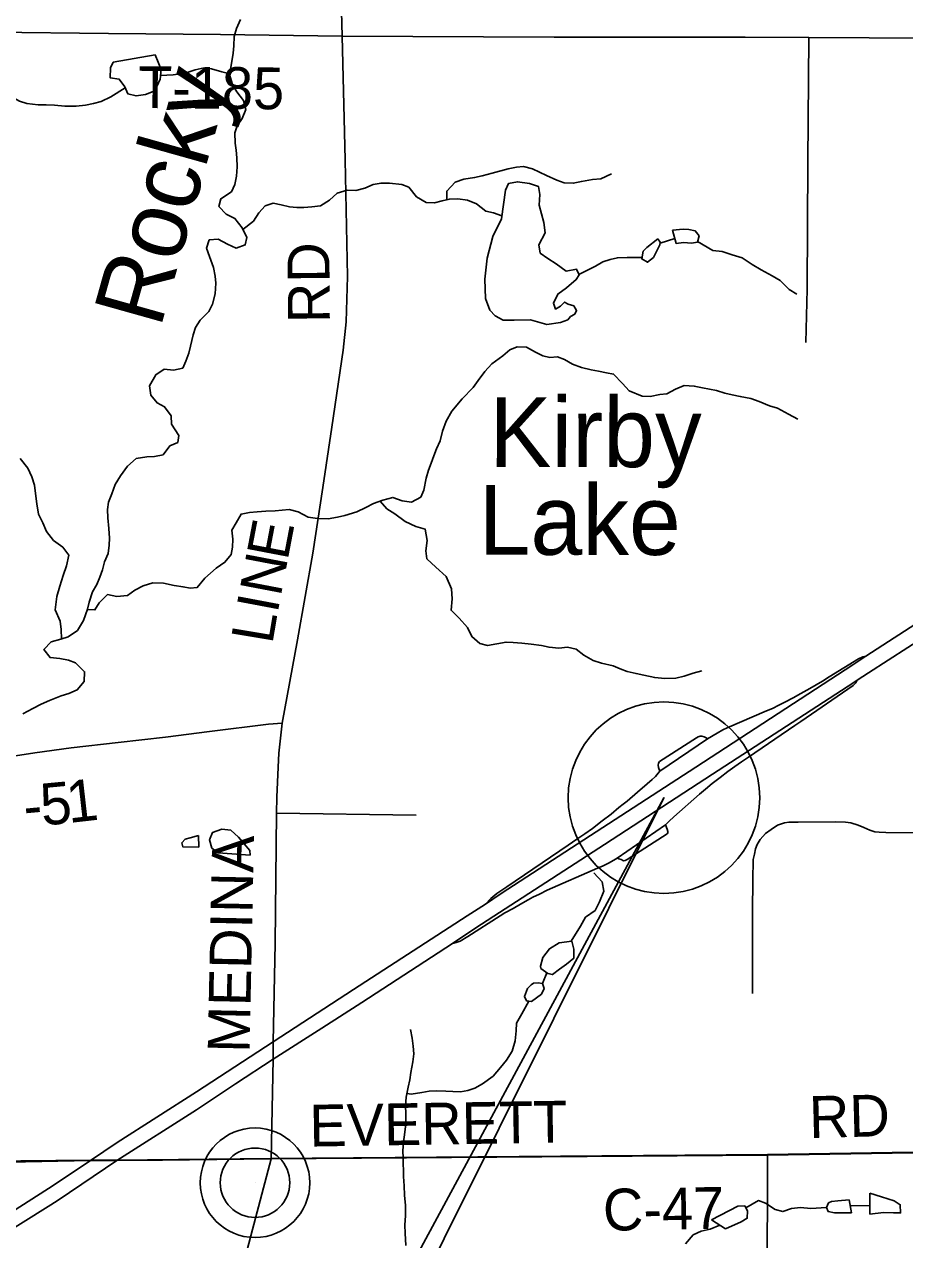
# Model space of a CAD drawing. Extents: x 0 to 34, y 0 to 22.
# Drawn here: x 3.335 to 4.531, y 15.737 to 17.388 of the extents above; entities that cross this region are included whole.
import ezdxf

# ---------------------------------------------------------------- set-up
doc = ezdxf.new("R2010")
doc.units = 0
for name, color, linetype in [('Default', 7, 'Continuous'), ('GM_X_City_Street', 7, 'Continuous'), ('GM_X_County_Road', 7, 'Continuous'), ('GM_X_County_Road_Text', 7, 'Continuous'), ('GM_X_Interchange_Ramps', 7, 'Continuous'), ('GM_X_Interstate_Route', 7, 'Continuous'), ('GM_X_Minor_Lake', 7, 'Continuous'), ('GM_X_Minor_Lake_Text', 7, 'Continuous'), ('GM_X_Minor_River', 7, 'Continuous'), ('GM_X_Minor_River_Text', 7, 'Continuous'), ('GM_X_Township_Road', 7, 'Continuous'), ('GM_X_Township_Road_Text', 7, 'Continuous'), ('GM_X_Unincorporated', 7, 'Continuous'), ('GM_X_Unincorporated_Location', 7, 'Continuous'), ('SH_Text', 7, 'Continuous')]:
    doc.layers.add(name, color=color, linetype=linetype)

msp = doc.modelspace()

# ---------------------------------------------------------------- linework, layer by layer
at = {"layer": 'Default'}
for points in [[(8.1749, 20.9), (3.2826, 20.9), (3.2843, 20.6124), (3.2845, 20.5998), (3.2888, 19.8918), (3.2901, 19.68), (3.2904, 19.1173), (3.2907, 18.4315), (3.2837, 17.3796), (3.2835, 17.0107), (3.2832, 16.3898), (3.2829, 15.8433), (3.425, 15.8449), (3.4609, 15.8448), (3.6703, 15.8472), (4.3446, 15.8524), (4.6273, 15.8569)], [(4.6273, 15.8569), (4.3446, 15.8524), (3.6703, 15.8472), (3.4609, 15.8448), (3.425, 15.8449), (3.2829, 15.8433), (3.2815, 15.7537), (3.2811, 15.7294)]]:
    msp.add_lwpolyline(points, dxfattribs=at)
at = {"layer": 'GM_X_City_Street'}
for points in [[(4.3144, 17.371), (4.4011, 17.3704), (4.565, 17.3697), (4.7306, 17.3693), (4.8313, 17.369), (4.9137, 17.369), (5.0572, 17.3688), (5.2312, 17.368), (5.5132, 17.3677), (5.6583, 17.3669)], [(4.3971, 16.9558), (4.3986, 17.0284), (4.3994, 17.2015), (4.4011, 17.3704)]]:
    msp.add_lwpolyline(points, dxfattribs=at)
at = {"layer": 'GM_X_County_Road'}
for p, q in [((3.2874, 15.8416), (3.3366, 15.8426)), ((3.523, 15.845), (3.6705, 15.8466)), ((3.6705, 15.8466), (4.3448, 15.8518))]:
    msp.add_line(p, q, dxfattribs=at)
for points in [[(3.6705, 15.8466), (3.6732, 15.982), (3.6732, 16.0058), (3.6762, 16.1394), (3.6779, 16.3165), (3.6783, 16.338), (3.6799, 16.3788), (3.6811, 16.398), (3.6855, 16.4388), (3.7063, 16.5518), (3.727, 16.6698), (3.7407, 16.7588), (3.7529, 16.841), (3.7683, 16.9457), (3.7726, 16.984), (3.7741, 17.0458), (3.7712, 17.2044), (3.7668, 17.3723), (3.7653, 17.4403)], [(4.3448, 15.8518), (4.6275, 15.8563), (4.6374, 15.8565)], [(3.3366, 15.8426), (3.4252, 15.8444), (3.4611, 15.8443), (3.523, 15.845)], [(3.6249, 15.6727), (3.643, 15.7419), (3.6705, 15.8466)], [(4.3329, 14.1), (4.3329, 14.1015), (4.3366, 14.4752), (4.338, 14.6961), (4.3387, 14.7484), (4.3392, 14.8357), (4.3412, 14.9346), (4.3421, 15.043), (4.3424, 15.2273), (4.3441, 15.44), (4.3442, 15.525), (4.3442, 15.6692), (4.3448, 15.8518)]]:
    msp.add_lwpolyline(points, dxfattribs=at)
at = {"layer": 'GM_X_Interchange_Ramps'}
for points in [[(4.4783, 16.5295), (4.4743, 16.5288), (4.4685, 16.526), (4.4287, 16.5017), (4.4193, 16.4958), (4.4022, 16.4856), (4.3901, 16.4789), (4.3798, 16.4729), (4.3684, 16.4672), (4.3604, 16.4631), (4.3515, 16.4588), (4.3434, 16.4553), (4.2902, 16.4323), (4.2841, 16.4294), (4.2762, 16.4251), (4.2632, 16.4175), (4.1985, 16.3736), (4.1963, 16.3708), (4.1926, 16.3664), (4.1881, 16.3621), (4.1812, 16.3561), (4.1682, 16.3449), (4.154, 16.3328), (4.1489, 16.3287), (4.143, 16.3239), (4.1323, 16.3148), (4.12, 16.3058), (4.1072, 16.2957), (4.0965, 16.2883), (4.0857, 16.2811), (4.0741, 16.2729), (3.9909, 16.2164), (3.9771, 16.2071), (3.9689, 16.2004), (3.9615, 16.1929)], [(3.9168, 16.1394), (3.9217, 16.1404), (3.9271, 16.1426), (3.9379, 16.1487), (3.9817, 16.1769), (3.9882, 16.1807), (3.9991, 16.1869), (4.0092, 16.1929), (4.0197, 16.1986), (4.0261, 16.2022), (4.0349, 16.2065), (4.0456, 16.2115), (4.1139, 16.2414), (4.1214, 16.2449), (4.1289, 16.2486), (4.1361, 16.2527), (4.1404, 16.2553), (4.2062, 16.3005), (4.2113, 16.3055), (4.2176, 16.3115), (4.2525, 16.3421), (4.2608, 16.349), (4.2698, 16.3565), (4.2804, 16.365), (4.291, 16.3729), (4.3002, 16.3797), (4.3095, 16.3861), (4.3189, 16.3926), (4.382, 16.4354), (4.3901, 16.441), (4.4614, 16.49), (4.4649, 16.4936), (4.4665, 16.4969)], [(4.2632, 16.4175), (4.2614, 16.4188), (4.2588, 16.4201), (4.2558, 16.4212), (4.2533, 16.421), (4.2508, 16.4203), (4.2483, 16.4186), (4.1982, 16.3864), (4.1967, 16.3844), (4.1963, 16.3817), (4.1967, 16.3786), (4.1985, 16.3736)], [(4.1404, 16.2553), (4.1428, 16.2545), (4.1459, 16.2534), (4.1493, 16.2518), (4.1515, 16.2519), (4.154, 16.2532), (4.2083, 16.2881), (4.2095, 16.2897), (4.2095, 16.2916), (4.2087, 16.2947), (4.2062, 16.3005)]]:
    msp.add_lwpolyline(points, dxfattribs=at)
at = {"layer": 'GM_X_Interstate_Route'}
for points in [[(3.2883, 15.7557), (3.3742, 15.8104), (3.4252, 15.8444), (3.4615, 15.8686), (3.5692, 15.9376), (3.6732, 16.0058), (3.7824, 16.0765), (3.9368, 16.1769), (3.9615, 16.1929), (3.983, 16.207), (4.0953, 16.2802), (4.2473, 16.3787), (4.4606, 16.518), (4.4783, 16.5295), (4.5617, 16.5838), (4.8848, 16.7932), (4.8864, 16.7942)], [(4.4623, 16.4941), (4.4665, 16.4969), (4.482, 16.5069), (4.562, 16.5585), (4.6393, 16.609)], [(3.7393, 16.0242), (3.7937, 16.0589), (3.9168, 16.1394), (3.9487, 16.1603), (4.1234, 16.2738), (4.2703, 16.3695), (4.4623, 16.4941)], [(3.6223, 15.9485), (3.6732, 15.982), (3.7393, 16.0242)], [(3.3812, 15.7905), (3.4611, 15.8443), (3.5689, 15.9133), (3.6223, 15.9485)], [(3.2884, 15.7323), (3.3713, 15.7839), (3.3812, 15.7905)]]:
    msp.add_lwpolyline(points, dxfattribs=at)
at = {"layer": 'GM_X_Minor_Lake'}
for points in [[(3.4559, 17.3368), (3.4522, 17.3292), (3.452, 17.3155), (3.4641, 17.3137), (3.4718, 17.3035), (3.4757, 17.2941), (3.4871, 17.2911), (3.5, 17.2928), (3.5124, 17.2982), (3.5199, 17.3139), (3.5209, 17.3268), (3.5128, 17.3469)], [(3.5128, 17.3469), (3.4559, 17.3368)], [(3.9834, 17.1241), (3.9715, 17.1), (3.9638, 17.0707), (3.961, 17.0422), (3.9616, 17.016), (3.9675, 17.0001), (3.9747, 16.9921), (3.9858, 16.9862), (4.0006, 16.9863), (4.023, 16.9869), (4.0451, 16.9803), (4.0636, 16.9831), (4.0735, 16.9866), (4.0772, 16.9912), (4.0829, 16.9947), (4.0855, 16.9993), (4.0816, 17.0057), (4.074, 17.0083), (4.0691, 17.0109), (4.0638, 17.0055), (4.057, 17.0013), (4.0539, 17.0096), (4.0602, 17.0218), (4.0719, 17.0303), (4.0851, 17.0414), (4.0888, 17.0479), (4.0854, 17.0555), (4.0713, 17.0531), (4.0576, 17.0628), (4.0465, 17.0703), (4.0362, 17.0775), (4.0342, 17.0885), (4.0428, 17.1049), (4.0408, 17.1189), (4.0345, 17.1428), (4.0355, 17.1569), (4.0339, 17.1679), (4.0217, 17.1719), (4.005, 17.1744), (3.9929, 17.172), (3.9888, 17.1629)], [(3.9888, 17.1629), (3.9834, 17.1241)], [(4.1807, 17.0853), (4.1758, 17.0799), (4.174, 17.0696), (4.1817, 17.0651), (4.19, 17.0717), (4.1955, 17.0824), (4.1985, 17.0885), (4.1989, 17.0923), (4.1958, 17.0968)], [(4.1958, 17.0968), (4.1807, 17.0853)], [(4.2209, 17.0906), (4.2308, 17.0918), (4.2414, 17.0908), (4.2497, 17.0924), (4.2519, 17.1011), (4.2466, 17.1076), (4.2378, 17.1094), (4.2302, 17.1101), (4.2158, 17.1088)], [(4.2158, 17.1088), (4.2209, 17.0906)], [(3.572, 16.2858), (3.5603, 16.283), (3.5538, 16.2811), (3.5493, 16.2761), (3.5505, 16.2708), (3.5725, 16.2702)], [(3.5725, 16.2702), (3.572, 16.2858)], [(3.6421, 16.2591), (3.6416, 16.2656), (3.6263, 16.2837), (3.6156, 16.2931), (3.6034, 16.2945), (3.591, 16.2902), (3.5869, 16.2799), (3.59, 16.2689), (3.5985, 16.2623)], [(3.5985, 16.2623), (3.6421, 16.2591)], [(4.0465, 16.0984), (4.0526, 16.0969), (4.0624, 16.1042), (4.0718, 16.1112), (4.0816, 16.1192), (4.0815, 16.1314), (4.0788, 16.1424), (4.0617, 16.1403), (4.0485, 16.1322), (4.0395, 16.1204)], [(4.0395, 16.1204), (4.0366, 16.1084), (4.0371, 16.1053), (4.0465, 16.0984)], [(4.0186, 16.078), (4.0146, 16.0673), (4.0176, 16.0613), (4.0241, 16.0606), (4.0377, 16.0702), (4.0414, 16.0782), (4.0391, 16.085)], [(4.0391, 16.085), (4.0333, 16.0858), (4.027, 16.0855), (4.0236, 16.0832), (4.0186, 16.078)], [(4.4557, 15.7911), (4.4402, 15.7894), (4.4318, 15.7886), (4.4277, 15.7866), (4.4251, 15.7805), (4.427, 15.7748), (4.4358, 15.7734), (4.4591, 15.7732)], [(4.4591, 15.7732), (4.4557, 15.7911)], [(4.4836, 15.7712), (4.5022, 15.7736), (4.5158, 15.773), (4.5257, 15.7731), (4.5252, 15.7841), (4.5168, 15.7897), (4.4997, 15.7949), (4.4837, 15.8001)], [(4.4837, 15.8001), (4.4836, 15.7712)], [(4.2876, 15.7515), (4.3091, 15.7608), (4.3174, 15.7658), (4.3177, 15.7761), (4.3139, 15.7825), (4.3044, 15.7824), (4.2689, 15.7639)], [(4.2689, 15.7639), (4.2876, 15.7515)]]:
    msp.add_lwpolyline(points, dxfattribs=at)
at = {"layer": 'GM_X_Minor_River'}
for points in [[(3.6288, 17.3951), (3.6236, 17.3825), (3.6203, 17.3718), (3.6197, 17.3593), (3.619, 17.349), (3.6165, 17.3353), (3.6139, 17.3201), (3.6179, 17.3068), (3.624, 17.2966)], [(3.6142, 17.3213), (3.6037, 17.3238), (3.5896, 17.3278), (3.5797, 17.3293), (3.5672, 17.3265), (3.5566, 17.323), (3.5468, 17.321), (3.5373, 17.3197), (3.5203, 17.3188)], [(3.4724, 17.3021), (3.4526, 17.2897), (3.4397, 17.2835), (3.4291, 17.2807), (3.4181, 17.2783), (3.4056, 17.2771), (3.3904, 17.2773), (3.3764, 17.2783), (3.365, 17.279), (3.354, 17.2792), (3.3388, 17.2806), (3.3285, 17.2839), (3.314, 17.2922), (3.3045, 17.294), (3.2877, 17.2925)], [(3.624, 17.2966), (3.6329, 17.2849), (3.636, 17.2728), (3.6312, 17.2602), (3.6244, 17.2506), (3.6211, 17.2407), (3.6216, 17.2271), (3.6228, 17.2172), (3.6237, 17.2069), (3.6242, 17.1948), (3.6235, 17.1819), (3.6214, 17.1708), (3.6165, 17.1609), (3.6022, 17.1513), (3.5996, 17.141), (3.6092, 17.1304), (3.6214, 17.1245), (3.631, 17.112), (3.6376, 17.0988), (3.6354, 17.0885), (3.6229, 17.0842), (3.6111, 17.0894), (3.5985, 17.0965), (3.5864, 17.0953), (3.5827, 17.0842), (3.5866, 17.0728), (3.592, 17.0577), (3.5944, 17.0463), (3.5952, 17.0364), (3.5946, 17.022), (3.5909, 17.0079), (3.5857, 16.998), (3.5741, 16.9865), (3.5677, 16.9762), (3.5644, 16.9666), (3.5611, 16.951), (3.5585, 16.9415), (3.5548, 16.9308), (3.5504, 16.9209), (3.5379, 16.9185), (3.525, 16.9199), (3.514, 16.9122), (3.5054, 16.8973), (3.5071, 16.8844), (3.5155, 16.8738), (3.5258, 16.8686), (3.5346, 16.8565), (3.5351, 16.8451), (3.5451, 16.8296), (3.5437, 16.8201), (3.5331, 16.8155), (3.5237, 16.8032), (3.512, 16.8012), (3.5017, 16.8007), (3.487, 16.7983), (3.4753, 16.788), (3.4659, 16.7746), (3.4584, 16.7631), (3.454, 16.7505), (3.4495, 16.7391), (3.4481, 16.7292), (3.4486, 16.7178), (3.4499, 16.7034), (3.4507, 16.6901), (3.4504, 16.6806), (3.449, 16.6692), (3.4442, 16.6577), (3.4416, 16.647), (3.4379, 16.6371), (3.4339, 16.6272), (3.4279, 16.6173), (3.4231, 16.6032), (3.4209, 16.5937), (3.4157, 16.578), (3.4075, 16.5647), (3.3946, 16.5562), (3.3848, 16.553), (3.3716, 16.5491), (3.3618, 16.5388), (3.3702, 16.5278), (3.3835, 16.5264), (3.3953, 16.5243), (3.4048, 16.5206), (3.4171, 16.5085), (3.4164, 16.4952), (3.4071, 16.4841), (3.3957, 16.4791), (3.3851, 16.4759), (3.3696, 16.4693), (3.3579, 16.4643), (3.3466, 16.4588), (3.333, 16.4515)], [(3.909, 17.1499), (3.9091, 17.1618), (3.9204, 17.174), (3.9325, 17.1779), (3.9469, 17.18), (3.9571, 17.1823), (3.9707, 17.1863), (3.9927, 17.1918), (4.0037, 17.1942), (4.0135, 17.195), (4.0257, 17.1921), (4.0352, 17.1873), (4.0448, 17.1828), (4.0585, 17.1768), (4.0684, 17.1728), (4.0809, 17.1725), (4.0919, 17.1749), (4.107, 17.1773), (4.1184, 17.1785), (4.1328, 17.1851)], [(3.6322, 17.1096), (3.6465, 17.1209), (3.6536, 17.132), (3.6626, 17.1416), (3.6732, 17.1455), (3.6842, 17.1429), (3.6956, 17.1404), (3.7055, 17.1393), (3.715, 17.1394), (3.7256, 17.1403), (3.7374, 17.1415), (3.7498, 17.1496), (3.7604, 17.1588), (3.7736, 17.1631), (3.7854, 17.1625), (3.7979, 17.1656), (3.8092, 17.1707), (3.8198, 17.1727), (3.8312, 17.1724), (3.8479, 17.1707), (3.8574, 17.1673), (3.8682, 17.1541), (3.8811, 17.1463), (3.8925, 17.146), (3.9028, 17.1484), (3.9126, 17.1508), (3.924, 17.1513), (3.9373, 17.1495), (3.9495, 17.1443), (3.9621, 17.1345), (3.9724, 17.132), (3.984, 17.1281)], [(4.1988, 17.0911), (4.2191, 17.0971)], [(4.2499, 17.0931), (4.2707, 17.0812), (4.2832, 17.0798), (4.2966, 17.0753), (4.3103, 17.0709), (4.324, 17.0619), (4.3362, 17.0548), (4.3511, 17.0466), (4.3621, 17.0402), (4.3744, 17.0282), (4.3847, 17.0218)], [(4.0886, 17.0485), (4.1111, 17.0599), (4.1209, 17.0657), (4.1312, 17.0689), (4.141, 17.0712), (4.1543, 17.0713), (4.1744, 17.0716)], [(3.4207, 16.593), (3.4311, 16.5926), (3.4367, 16.6022), (3.4484, 16.6133), (3.4609, 16.6108), (3.4754, 16.612), (3.4855, 16.6193), (3.4965, 16.6255), (3.5097, 16.6295), (3.5242, 16.6288), (3.5386, 16.6259), (3.5508, 16.6238), (3.5603, 16.6223), (3.5701, 16.6232), (3.5806, 16.6358), (3.5957, 16.6493), (3.6078, 16.6574), (3.616, 16.6677), (3.6182, 16.678), (3.6185, 16.6886), (3.6172, 16.7011), (3.6228, 16.7107), (3.6296, 16.7229), (3.6409, 16.7249), (3.6515, 16.7258), (3.6633, 16.7267), (3.6762, 16.7272), (3.6948, 16.7289), (3.7073, 16.7259), (3.7207, 16.7185), (3.7336, 16.7167), (3.748, 16.7164), (3.7605, 16.7185), (3.7707, 16.7208), (3.787, 16.7259), (3.7991, 16.7317), (3.8097, 16.7372), (3.8222, 16.7418), (3.8358, 16.7454), (3.8487, 16.7406), (3.8613, 16.7388), (3.8737, 16.7457), (3.8778, 16.7553), (3.8811, 16.7716), (3.8844, 16.7823), (3.8877, 16.7918), (3.8914, 16.8021), (3.8952, 16.8117), (3.9, 16.8224), (3.9033, 16.8357), (3.9081, 16.849), (3.9159, 16.8628), (3.9302, 16.8793), (3.9449, 16.895), (3.9516, 16.9045), (3.9606, 16.9164), (3.9704, 16.9271), (3.9851, 16.9379), (3.9949, 16.946), (4.0047, 16.9499), (4.0176, 16.9496), (4.0298, 16.9429), (4.0394, 16.938), (4.0493, 16.9355), (4.0595, 16.9367), (4.069, 16.933), (4.0801, 16.9266), (4.0919, 16.9222), (4.1052, 16.9189), (4.1151, 16.9171), (4.1261, 16.9149), (4.1356, 16.9131), (4.1479, 16.9003), (4.157, 16.8901), (4.1746, 16.8831), (4.1852, 16.8828), (4.1985, 16.8852), (4.2079, 16.8864), (4.2196, 16.8926), (4.2314, 16.8977), (4.2454, 16.8967), (4.2564, 16.8945), (4.2754, 16.8909), (4.2869, 16.8872), (4.2967, 16.885), (4.3078, 16.8828), (4.3222, 16.8799), (4.3333, 16.8758), (4.3477, 16.8699), (4.3584, 16.8666), (4.3733, 16.8587), (4.3858, 16.852)], [(3.3858, 16.5534), (3.3851, 16.566), (3.3838, 16.5774), (3.3772, 16.5925), (3.3794, 16.6107), (3.3834, 16.6248), (3.3882, 16.6393), (3.3926, 16.6523), (3.3955, 16.6668), (3.3875, 16.6777), (3.3749, 16.6871), (3.3653, 16.6991), (3.3602, 16.7109), (3.3544, 16.7226), (3.3524, 16.7366), (3.3508, 16.7473), (3.3492, 16.7621), (3.3453, 16.7734), (3.3402, 16.7852), (3.3295, 16.7984)], [(3.8186, 16.7405), (3.8276, 16.7301), (3.8387, 16.723), (3.8528, 16.7129), (3.8669, 16.7058), (3.8798, 16.7021), (3.8826, 16.6869), (3.8808, 16.6728), (3.8821, 16.6622), (3.8943, 16.6506), (3.9081, 16.6378), (3.9155, 16.6211), (3.9163, 16.6078), (3.915, 16.5922), (3.9261, 16.5813), (3.9372, 16.5689), (3.943, 16.5564), (3.9541, 16.547), (3.9643, 16.5444), (3.9772, 16.5465), (3.9897, 16.5489), (3.9992, 16.5482), (4.011, 16.5472), (4.0239, 16.5461), (4.038, 16.544), (4.0482, 16.5418), (4.0615, 16.5408), (4.0729, 16.542), (4.0851, 16.5391), (4.0954, 16.5312), (4.108, 16.5238), (4.1194, 16.5204), (4.135, 16.5164), (4.1445, 16.5123), (4.154, 16.509), (4.1662, 16.5061), (4.1768, 16.5039), (4.1917, 16.5006), (4.2053, 16.4992), (4.2201, 16.4997), (4.2315, 16.5025), (4.2436, 16.5068), (4.2557, 16.5099)], [(4.0782, 16.1423), (4.0907, 16.163), (4.0975, 16.1749), (4.1106, 16.1841), (4.1166, 16.1959), (4.1226, 16.2104), (4.1202, 16.2229), (4.1091, 16.2354)], [(4.045, 16.0995), (4.0391, 16.085)], [(3.8551, 15.9355), (3.8609, 15.9344), (3.8753, 15.9368), (3.8852, 15.9384), (3.8958, 15.9389), (3.9076, 15.9387), (3.9174, 15.938), (3.9277, 15.9377), (3.9375, 15.9393), (3.9474, 15.9428), (3.9576, 15.9486), (3.9723, 15.959), (3.982, 15.9705), (3.9903, 15.9805), (3.9978, 15.9931), (4.0022, 16.0068), (4.0032, 16.0205), (4.0039, 16.0311), (4.011, 16.0437), (4.0205, 16.061)], [(3.8537, 15.7288), (3.8528, 15.7455), (3.8523, 15.7565), (3.8529, 15.7695), (3.8532, 15.7831), (3.8519, 15.7972), (3.851, 15.8101), (3.8502, 15.8226), (3.8499, 15.8481), (3.8495, 15.8576), (3.8505, 15.8697), (3.8516, 15.8792), (3.8533, 15.8941), (3.8536, 15.9081), (3.8531, 15.9184), (3.8541, 15.9302), (3.8567, 15.9439), (3.8589, 15.9538), (3.8603, 15.9637), (3.8632, 15.9785), (3.8642, 15.9892), (3.8634, 15.9998), (3.8621, 16.0108), (3.8598, 16.0222)], [(4.3155, 15.7798), (4.3328, 15.7899), (4.3423, 15.7862), (4.3553, 15.7776), (4.3655, 15.775), (4.3773, 15.7789), (4.3898, 15.7806), (4.4035, 15.7792), (4.4251, 15.7804)], [(4.4836, 15.7831), (4.4573, 15.7828)], [(4.2335, 15.7312), (4.244, 15.7431), (4.2546, 15.7485), (4.2667, 15.7509), (4.2799, 15.7566)]]:
    msp.add_lwpolyline(points, dxfattribs=at)
at = {"layer": 'GM_X_Township_Road'}
msp.add_line((3.6779, 16.3165), (3.8674, 16.3138), dxfattribs=at)
for points in [[(3.292, 17.3777), (3.4496, 17.376), (3.6018, 17.3747), (3.7668, 17.3723)], [(3.7668, 17.3723), (4.055, 17.3709), (4.3144, 17.371)], [(3.2904, 16.3891), (3.3494, 16.3984), (3.399, 16.4052), (3.4626, 16.4122), (3.5271, 16.4197), (3.5869, 16.4272), (3.667, 16.4371), (3.6855, 16.4388)], [(4.3246, 16.0713), (4.3246, 16.1645), (4.3246, 16.1772), (4.325, 16.2312), (4.3254, 16.2473), (4.3254, 16.2535), (4.327, 16.2608), (4.3284, 16.2678), (4.3309, 16.2739), (4.335, 16.2804), (4.3423, 16.2888), (4.3497, 16.2941), (4.3585, 16.2999), (4.3677, 16.3031), (4.374, 16.3042), (4.3863, 16.3039), (4.4366, 16.3044), (4.4507, 16.304), (4.4582, 16.3031), (4.4678, 16.3001), (4.4758, 16.297), (4.4838, 16.2933), (4.4905, 16.2909), (4.4965, 16.2907), (4.5055, 16.2901), (4.5618, 16.2896)]]:
    msp.add_lwpolyline(points, dxfattribs=at)
at = {"layer": 'GM_X_Unincorporated'}
for radius in [0.0744, 0.0472]:
    msp.add_circle((3.6486, 15.8141), radius, dxfattribs=at)
at = {"layer": 'GM_X_Unincorporated_Location'}
msp.add_line((3.6486, 15.8141), (3.6486, 15.8141), dxfattribs=at)
at = {"layer": 'SH_Text'}
msp.add_lwpolyline([(2.8604, 13.8477), (4.2041, 16.3374), (2.8604, 13.6417)], close=True, dxfattribs=at)
msp.add_circle((4.2041, 16.3374), 0.1301, dxfattribs=at)

# ---------------------------------------------------------------- texts
at = {"layer": 'GM_X_County_Road_Text'}
for s, height, rotation, p in [('RD', 0.05682, 90.4221, (3.7503, 16.9826)), ('E', 0.0568, 79.1876, (3.6928, 16.6586)), ('N', 0.0568, 79.1901, (3.6834, 16.6095)), ('I', 0.0568, 79.307, (3.6791, 16.5866)), ('L', 0.0568, 80.513, (3.6721, 16.545)), ('MEDINA', 0.05682, 88.7925, (3.6411, 15.9903)), ('EVERETT', 0.05682, 0.9291, (3.7229, 15.8632)), ('RD', 0.05682, 1.4807, (4.4019, 15.8748)), ('C-47', 0.05682, 1.0286, (4.1217, 15.7488))]:
    msp.add_text(s, height=height, rotation=rotation, dxfattribs=at).set_placement(p)
at = {"layer": 'GM_X_Minor_Lake_Text'}
for s, rotation, p in [('Kirby', 359.9309, (3.9667, 16.7868)), ('Lake', 359.9302, (3.9523, 16.6676))]:
    msp.add_text(s, height=0.09474, rotation=rotation, dxfattribs=at).set_placement(p)
at = {"layer": 'GM_X_Minor_River_Text'}
msp.add_text('Rocky', height=0.09475, rotation=74.3271, dxfattribs=at).set_placement((3.5199, 16.9739))
at = {"layer": 'GM_X_Township_Road_Text'}
for s, height, rotation, p in [('T-185', 0.05682, 359.4355, (3.4895, 17.2747)), ('5', 0.0568, 5.4351, (3.3597, 16.2994)), ('1', 0.0568, 6.4821, (3.3957, 16.3029)), ('-', 0.0568, 5.2485, (3.3363, 16.2973))]:
    msp.add_text(s, height=height, rotation=rotation, dxfattribs=at).set_placement(p)

doc.saveas('drawing.dxf')
